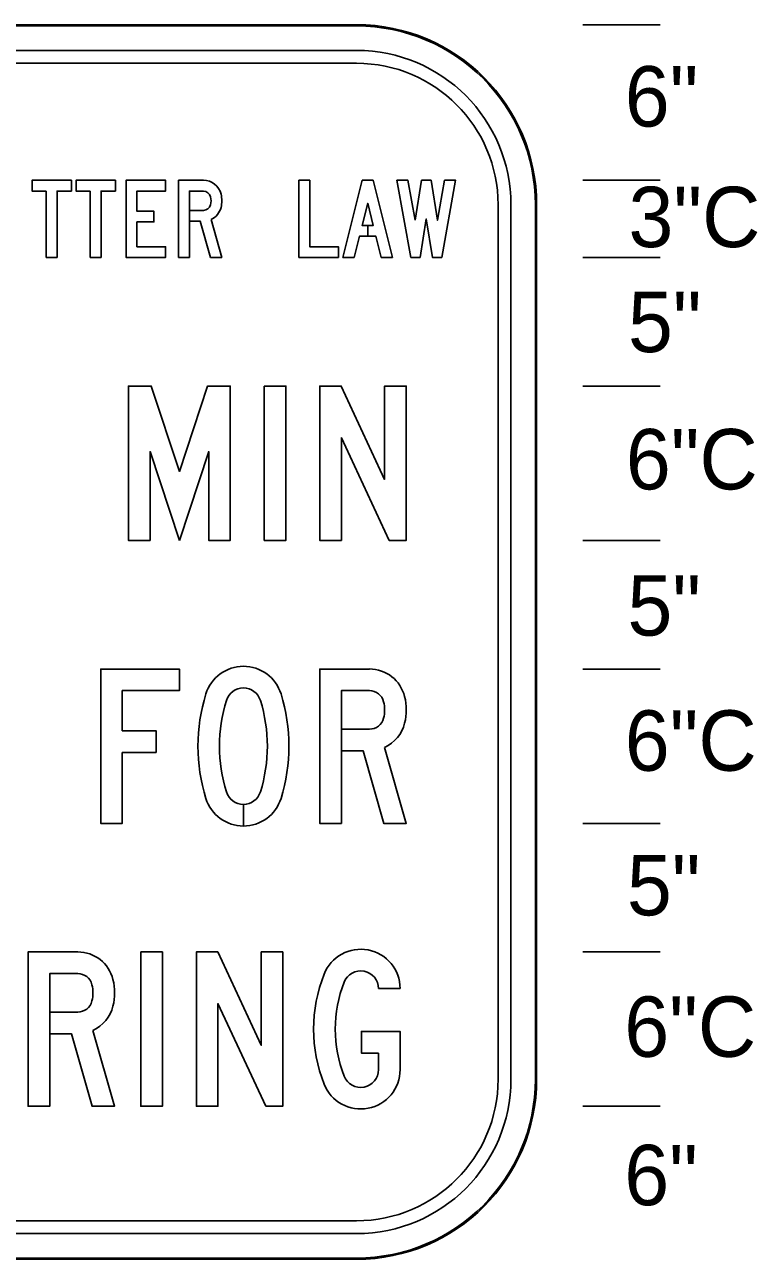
# Model space of a CAD drawing. Extents: x 0 to 770, y 0 to 495.
# Drawn here: x 668.7 to 711.2, y 64.1 to 135.7 of the extents above; entities that cross this region are included whole.
import ezdxf

# ---------------------------------------------------------------- set-up
doc = ezdxf.new("R2010")
doc.units = 0
for name, color, linetype in [('GSBWFill', 7, 'Continuous'), ('GSColorFill', 7, 'Continuous'), ('GSDims', 7, 'Continuous'), ('GSOutline', 7, 'Continuous'), ('TextStructures', 7, 'Continuous')]:
    doc.layers.add(name, color=color, linetype=linetype)

msp = doc.modelspace()

# ---------------------------------------------------------------- linework, layer by layer
at = {"layer": 'GSBWFill'}
for p, q in [((687.955, 135.665), (646.215, 135.665)), ((687.955, 134.174), (646.215, 134.174)), ((646.215, 133.429), (687.955, 133.429)), ((696.154, 125.23), (696.154, 74.545)), ((696.899, 74.545), (696.899, 125.23)), ((698.39, 74.545), (698.39, 125.23)), ((679.076, 124.902), (679.076, 124.902)), ((688.697, 94.834), (688.697, 94.834)), ((681.396, 90.474), (681.396, 89.222)), ((681.396, 89.222), (681.396, 90.474)), ((689.222, 79.8), (690.474, 79.8)), ((671.792, 78.436), (671.792, 78.436)), ((689.222, 76.066), (689.222, 75.104)), ((687.955, 66.346), (646.222, 66.346)), ((646.222, 65.601), (687.955, 65.601)), ((646.215, 64.11), (687.955, 64.11))]:
    msp.add_line(p, q, dxfattribs=at)
for points in [[(669.969, 126.02), (669.142, 126.02), (669.142, 126.646), (671.423, 126.646), (671.423, 126.02), (670.595, 126.02), (670.595, 122.174), (669.969, 122.174)], [(672.518, 126.02), (671.691, 126.02), (671.691, 126.646), (673.972, 126.646), (673.972, 126.02), (673.144, 126.02), (673.144, 122.174), (672.518, 122.174)], [(675.224, 122.8), (675.224, 124.231), (676.204, 124.231), (676.204, 124.857), (675.224, 124.857), (675.224, 126.02), (676.879, 126.02), (676.879, 126.646), (674.598, 126.646), (674.598, 122.174), (676.879, 122.174), (676.879, 122.8)], [(684.615, 126.646), (685.242, 126.646), (685.242, 122.8), (686.896, 122.8), (686.896, 122.174), (684.615, 122.174)], [(688.596, 124.03), (688.274, 124.03), (688.596, 125.317), (688.917, 124.03), (688.596, 124.03), (688.596, 123.404), (689.074, 123.404), (689.381, 122.174), (690.027, 122.174), (688.909, 126.646), (688.283, 126.646), (687.165, 122.174), (687.81, 122.174), (688.117, 123.404), (688.596, 123.404)], [(691.348, 124.332), (691.718, 126.646), (692.271, 126.646), (692.641, 124.332), (693.058, 126.646), (693.694, 126.646), (692.889, 122.174), (692.352, 122.174), (691.995, 124.41), (691.637, 122.174), (691.1, 122.174), (690.295, 126.646), (690.931, 126.646)], [(677.684, 105.776), (679.383, 110.926), (679.383, 105.776), (680.635, 105.776), (680.635, 114.72), (679.317, 114.72), (677.684, 109.772), (676.051, 114.72), (674.732, 114.72), (674.732, 105.776), (675.984, 105.776), (675.984, 110.926)], [(682.603, 114.72), (683.855, 114.72), (683.855, 105.776), (682.603, 105.776)], [(689.848, 105.776), (690.832, 105.776), (690.832, 114.72), (689.58, 114.72), (689.58, 109.315), (687.06, 114.72), (685.823, 114.72), (685.823, 105.776), (687.075, 105.776), (687.075, 111.724)], [(674.374, 93.493), (676.334, 93.493), (676.334, 94.745), (674.374, 94.745), (674.374, 97.07), (677.684, 97.07), (677.684, 98.322), (673.122, 98.322), (673.122, 89.378), (674.374, 89.378)], [(675.448, 81.925), (676.7, 81.925), (676.7, 72.98), (675.448, 72.98)], [(682.692, 72.98), (683.676, 72.98), (683.676, 81.925), (682.424, 81.925), (682.424, 76.52), (679.905, 81.925), (678.668, 81.925), (678.668, 72.98), (679.92, 72.98), (679.92, 78.928)]]:
    msp.add_lwpolyline(points, close=True, dxfattribs=at)
for points in [[(679.076, 126.02), (678.265, 126.02), (678.265, 122.174), (677.639, 122.174), (677.639, 126.646), (679.076, 126.646)], [(679.517, 124.373), (680.143, 122.174), (679.492, 122.174), (678.894, 124.276), (678.265, 124.276), (678.265, 124.902), (679.076, 124.902)], [(688.697, 97.07), (687.075, 97.07), (687.075, 89.378), (685.823, 89.378), (685.823, 98.322), (688.697, 98.322)], [(689.58, 93.776), (690.832, 89.378), (689.53, 89.378), (688.333, 93.582), (687.076, 93.582), (687.076, 94.834), (688.697, 94.834)], [(671.792, 80.672), (670.17, 80.672), (670.17, 72.98), (668.918, 72.98), (668.918, 81.925), (671.792, 81.925)], [(672.675, 77.378), (673.927, 72.98), (672.625, 72.98), (671.428, 77.184), (670.171, 77.184), (670.171, 78.436), (671.792, 78.436)], [(690.474, 75.104), (690.474, 77.318), (688.238, 77.318), (688.238, 76.066), (689.222, 76.066)]]:
    msp.add_lwpolyline(points, dxfattribs=at)
for centre, radius, start, end in [((687.955, 125.23), 10.435, 0, 90), ((687.955, 125.23), 8.944, 0, 90), ((687.955, 125.23), 8.199, 0, 90), ((679.076, 125.595), 1.051, 13.88654, 90), ((679.076, 125.595), 0.425, 13.88654, 90), ((679.076, 125.327), 0.425, 270, 346.11346), ((678.533, 125.461), 0.984, 346.11346, 13.88654), ((678.533, 125.461), 1.61, 346.11346, 13.88654), ((679.076, 125.327), 1.051, 294.82206, 346.11346), ((681.396, 96.198), 2.281, 17.32827, 162.67173), ((688.697, 96.221), 2.102, 13.88654, 90), ((688.921, 93.85), 10.164, 162.67173, 197.32827), ((681.396, 96.198), 1.029, 17.32827, 162.67173), ((673.87, 93.85), 10.164, 342.67173, 17.32827), ((688.697, 96.221), 0.85, 13.88654, 90), ((687.612, 95.952), 3.22, 346.11346, 13.88654), ((688.921, 93.85), 8.911, 162.67173, 197.32827), ((673.87, 93.85), 8.911, 342.67173, 17.32827), ((687.612, 95.952), 1.968, 346.11346, 13.88654), ((688.697, 95.684), 0.85, 270, 346.11346), ((688.697, 95.684), 2.102, 294.82206, 346.11346), ((681.396, 91.502), 1.029, 197.32827, 270), ((681.396, 91.502), 1.029, 270.02491, 342.67173), ((681.396, 91.502), 2.281, 197.32827, 270), ((681.396, 91.502), 2.281, 270.01123, 342.67173), ((671.792, 79.823), 2.102, 13.88654, 90), ((688.193, 79.8), 2.281, 0, 158.43141), ((671.792, 79.823), 0.85, 13.88654, 90), ((670.707, 79.554), 3.22, 346.11346, 13.88654), ((694.133, 77.452), 8.668, 158.43141, 201.5686), ((694.133, 77.452), 7.415, 158.4314, 201.56859), ((688.193, 79.8), 1.029, 0, 158.43141), ((670.707, 79.554), 1.968, 346.11346, 13.88654), ((671.792, 79.286), 0.85, 270, 346.11346), ((671.792, 79.286), 2.102, 294.82206, 346.11346), ((688.193, 75.104), 2.281, 201.56859, 0), ((688.193, 75.104), 1.029, 201.56859, 0), ((687.955, 74.545), 8.944, 270, 0), ((687.955, 74.545), 8.199, 270, 0), ((687.955, 74.545), 10.435, 270, 0)]:
    msp.add_arc(centre, radius, start, end, dxfattribs=at)
at = {"layer": 'GSColorFill'}
for p, q in [((687.955, 135.665), (646.215, 135.665)), ((687.955, 135.665), (646.215, 135.665)), ((646.215, 135.59), (687.955, 135.59)), ((687.955, 134.174), (646.215, 134.174)), ((646.215, 133.429), (687.955, 133.429)), ((696.154, 125.23), (696.154, 74.545)), ((696.899, 74.545), (696.899, 125.23)), ((698.315, 125.23), (698.315, 74.545)), ((698.39, 74.545), (698.39, 125.23)), ((698.39, 74.545), (698.39, 125.23)), ((679.076, 124.902), (679.076, 124.902)), ((688.697, 94.834), (688.697, 94.834)), ((681.396, 90.474), (681.396, 89.222)), ((681.396, 89.222), (681.396, 90.474)), ((689.222, 79.8), (690.474, 79.8)), ((671.792, 78.436), (671.792, 78.436)), ((689.222, 76.066), (689.222, 75.104)), ((687.955, 66.346), (646.222, 66.346)), ((646.222, 65.601), (687.955, 65.601)), ((687.955, 64.185), (646.215, 64.185)), ((646.215, 64.11), (687.955, 64.11)), ((646.215, 64.11), (687.955, 64.11))]:
    msp.add_line(p, q, dxfattribs=at)
for points in [[(669.969, 126.02), (669.142, 126.02), (669.142, 126.646), (671.423, 126.646), (671.423, 126.02), (670.595, 126.02), (670.595, 122.174), (669.969, 122.174)], [(672.518, 126.02), (671.691, 126.02), (671.691, 126.646), (673.972, 126.646), (673.972, 126.02), (673.144, 126.02), (673.144, 122.174), (672.518, 122.174)], [(675.224, 122.8), (675.224, 124.231), (676.204, 124.231), (676.204, 124.857), (675.224, 124.857), (675.224, 126.02), (676.879, 126.02), (676.879, 126.646), (674.598, 126.646), (674.598, 122.174), (676.879, 122.174), (676.879, 122.8)], [(684.615, 126.646), (685.242, 126.646), (685.242, 122.8), (686.896, 122.8), (686.896, 122.174), (684.615, 122.174)], [(688.596, 124.03), (688.274, 124.03), (688.596, 125.317), (688.917, 124.03), (688.596, 124.03), (688.596, 123.404), (689.074, 123.404), (689.381, 122.174), (690.027, 122.174), (688.909, 126.646), (688.283, 126.646), (687.165, 122.174), (687.81, 122.174), (688.117, 123.404), (688.596, 123.404)], [(691.348, 124.332), (691.718, 126.646), (692.271, 126.646), (692.641, 124.332), (693.058, 126.646), (693.694, 126.646), (692.889, 122.174), (692.352, 122.174), (691.995, 124.41), (691.637, 122.174), (691.1, 122.174), (690.295, 126.646), (690.931, 126.646)], [(677.684, 105.776), (679.383, 110.926), (679.383, 105.776), (680.635, 105.776), (680.635, 114.72), (679.317, 114.72), (677.684, 109.772), (676.051, 114.72), (674.732, 114.72), (674.732, 105.776), (675.984, 105.776), (675.984, 110.926)], [(682.603, 114.72), (683.855, 114.72), (683.855, 105.776), (682.603, 105.776)], [(689.848, 105.776), (690.832, 105.776), (690.832, 114.72), (689.58, 114.72), (689.58, 109.315), (687.06, 114.72), (685.823, 114.72), (685.823, 105.776), (687.075, 105.776), (687.075, 111.724)], [(674.374, 93.493), (676.334, 93.493), (676.334, 94.745), (674.374, 94.745), (674.374, 97.07), (677.684, 97.07), (677.684, 98.322), (673.122, 98.322), (673.122, 89.378), (674.374, 89.378)], [(675.448, 81.925), (676.7, 81.925), (676.7, 72.98), (675.448, 72.98)], [(682.692, 72.98), (683.676, 72.98), (683.676, 81.925), (682.424, 81.925), (682.424, 76.52), (679.905, 81.925), (678.668, 81.925), (678.668, 72.98), (679.92, 72.98), (679.92, 78.928)]]:
    msp.add_lwpolyline(points, close=True, dxfattribs=at)
for points in [[(679.076, 126.02), (678.265, 126.02), (678.265, 122.174), (677.639, 122.174), (677.639, 126.646), (679.076, 126.646)], [(679.517, 124.373), (680.143, 122.174), (679.492, 122.174), (678.894, 124.276), (678.265, 124.276), (678.265, 124.902), (679.076, 124.902)], [(688.697, 97.07), (687.075, 97.07), (687.075, 89.378), (685.823, 89.378), (685.823, 98.322), (688.697, 98.322)], [(689.58, 93.776), (690.832, 89.378), (689.53, 89.378), (688.333, 93.582), (687.076, 93.582), (687.076, 94.834), (688.697, 94.834)], [(671.792, 80.672), (670.17, 80.672), (670.17, 72.98), (668.918, 72.98), (668.918, 81.925), (671.792, 81.925)], [(672.675, 77.378), (673.927, 72.98), (672.625, 72.98), (671.428, 77.184), (670.171, 77.184), (670.171, 78.436), (671.792, 78.436)], [(690.474, 75.104), (690.474, 77.318), (688.238, 77.318), (688.238, 76.066), (689.222, 76.066)]]:
    msp.add_lwpolyline(points, dxfattribs=at)
for centre, radius, start, end in [((687.955, 125.23), 10.435, 0, 90), ((687.955, 125.23), 10.435, 0, 90), ((687.955, 125.23), 10.361, 0, 90), ((687.955, 125.23), 8.944, 0, 90), ((687.955, 125.23), 8.199, 0, 90), ((679.076, 125.595), 1.051, 13.88654, 90), ((679.076, 125.595), 0.425, 13.88654, 90), ((679.076, 125.327), 0.425, 270, 346.11346), ((678.533, 125.461), 0.984, 346.11346, 13.88654), ((678.533, 125.461), 1.61, 346.11346, 13.88654), ((679.076, 125.327), 1.051, 294.82206, 346.11346), ((681.396, 96.198), 2.281, 17.32827, 162.67173), ((688.697, 96.221), 2.102, 13.88654, 90), ((688.921, 93.85), 10.164, 162.67173, 197.32827), ((681.396, 96.198), 1.029, 17.32827, 162.67173), ((673.87, 93.85), 10.164, 342.67173, 17.32827), ((688.697, 96.221), 0.85, 13.88654, 90), ((687.612, 95.952), 3.22, 346.11346, 13.88654), ((688.921, 93.85), 8.911, 162.67173, 197.32827), ((673.87, 93.85), 8.911, 342.67173, 17.32827), ((687.612, 95.952), 1.968, 346.11346, 13.88654), ((688.697, 95.684), 0.85, 270, 346.11346), ((688.697, 95.684), 2.102, 294.82206, 346.11346), ((681.396, 91.502), 1.029, 197.32827, 270), ((681.396, 91.502), 1.029, 270.02491, 342.67173), ((681.396, 91.502), 2.281, 197.32827, 270), ((681.396, 91.502), 2.281, 270.01123, 342.67173), ((671.792, 79.823), 2.102, 13.88654, 90), ((688.193, 79.8), 2.281, 0, 158.43141), ((671.792, 79.823), 0.85, 13.88654, 90), ((670.707, 79.554), 3.22, 346.11346, 13.88654), ((694.133, 77.452), 8.668, 158.43141, 201.5686), ((694.133, 77.452), 7.415, 158.4314, 201.56859), ((688.193, 79.8), 1.029, 0, 158.43141), ((670.707, 79.554), 1.968, 346.11346, 13.88654), ((671.792, 79.286), 0.85, 270, 346.11346), ((671.792, 79.286), 2.102, 294.82206, 346.11346), ((688.193, 75.104), 2.281, 201.56859, 0), ((688.193, 75.104), 1.029, 201.56859, 0), ((687.955, 74.545), 10.435, 270, 0), ((687.955, 74.545), 8.944, 270, 0), ((687.955, 74.545), 8.199, 270, 0), ((687.955, 74.545), 10.435, 270, 0), ((687.955, 74.545), 10.361, 270, 0)]:
    msp.add_arc(centre, radius, start, end, dxfattribs=at)
at = {"layer": 'GSDims'}
for p, q in [((701.073, 135.665), (705.545, 135.665)), ((701.073, 126.646), (705.545, 126.646)), ((701.073, 126.646), (705.545, 126.646)), ((701.073, 122.174), (705.545, 122.174)), ((701.073, 122.174), (705.545, 122.174)), ((701.073, 114.72), (705.545, 114.72)), ((701.073, 114.72), (705.545, 114.72)), ((701.073, 105.776), (705.545, 105.776)), ((701.073, 105.776), (705.545, 105.776)), ((701.073, 98.322), (705.545, 98.322)), ((701.073, 98.322), (705.545, 98.322)), ((701.073, 89.378), (705.545, 89.378)), ((701.073, 89.378), (705.545, 89.378)), ((701.073, 81.925), (705.545, 81.925)), ((701.073, 81.925), (705.545, 81.925)), ((701.073, 72.98), (705.545, 72.98)), ((701.073, 72.98), (705.545, 72.98))]:
    msp.add_line(p, q, dxfattribs=at)
at = {"layer": 'GSOutline'}
for p, q in [((687.955, 135.665), (646.215, 135.665)), ((687.955, 134.174), (646.215, 134.174)), ((687.955, 133.429), (646.215, 133.429)), ((679.076, 126.646), (677.639, 126.646)), ((679.076, 126.02), (679.076, 126.02)), ((696.154, 74.545), (696.154, 125.23)), ((696.899, 74.545), (696.899, 125.23)), ((698.39, 74.545), (698.39, 125.23)), ((688.697, 98.322), (685.823, 98.322)), ((688.697, 97.07), (688.697, 97.07)), ((671.792, 81.925), (668.918, 81.925)), ((671.792, 80.672), (671.792, 80.672)), ((689.222, 79.8), (690.474, 79.8)), ((689.222, 76.066), (689.222, 75.104)), ((646.215, 66.346), (687.955, 66.346)), ((646.215, 65.601), (687.955, 65.601)), ((646.215, 64.11), (687.955, 64.11))]:
    msp.add_line(p, q, dxfattribs=at)
for points in [[(669.969, 126.02), (669.142, 126.02), (669.142, 126.646), (671.423, 126.646), (671.423, 126.02), (670.595, 126.02), (670.595, 122.174), (669.969, 122.174)], [(672.518, 126.02), (671.691, 126.02), (671.691, 126.646), (673.972, 126.646), (673.972, 126.02), (673.144, 126.02), (673.144, 122.174), (672.518, 122.174)], [(675.224, 122.8), (675.224, 124.231), (676.204, 124.231), (676.204, 124.857), (675.224, 124.857), (675.224, 126.02), (676.879, 126.02), (676.879, 126.646), (674.598, 126.646), (674.598, 122.174), (676.879, 122.174), (676.879, 122.8)], [(684.615, 126.646), (685.242, 126.646), (685.242, 122.8), (686.896, 122.8), (686.896, 122.174), (684.615, 122.174)], [(688.117, 123.404), (689.074, 123.404), (689.381, 122.174), (690.027, 122.174), (688.909, 126.646), (688.283, 126.646), (687.165, 122.174), (687.81, 122.174)], [(691.348, 124.332), (691.718, 126.646), (692.271, 126.646), (692.641, 124.332), (693.058, 126.646), (693.694, 126.646), (692.889, 122.174), (692.352, 122.174), (691.995, 124.41), (691.637, 122.174), (691.1, 122.174), (690.295, 126.646), (690.931, 126.646)], [(688.917, 124.03), (688.596, 125.317), (688.274, 124.03)], [(677.684, 105.776), (679.383, 110.926), (679.383, 105.776), (680.635, 105.776), (680.635, 114.72), (679.317, 114.72), (677.684, 109.772), (676.051, 114.72), (674.732, 114.72), (674.732, 105.776), (675.984, 105.776), (675.984, 110.926)], [(682.603, 114.72), (683.855, 114.72), (683.855, 105.776), (682.603, 105.776)], [(689.848, 105.776), (690.832, 105.776), (690.832, 114.72), (689.58, 114.72), (689.58, 109.315), (687.06, 114.72), (685.823, 114.72), (685.823, 105.776), (687.075, 105.776), (687.075, 111.724)], [(674.374, 93.493), (676.334, 93.493), (676.334, 94.745), (674.374, 94.745), (674.374, 97.07), (677.684, 97.07), (677.684, 98.322), (673.122, 98.322), (673.122, 89.378), (674.374, 89.378)], [(675.448, 81.925), (676.7, 81.925), (676.7, 72.98), (675.448, 72.98)], [(682.692, 72.98), (683.676, 72.98), (683.676, 81.925), (682.424, 81.925), (682.424, 76.52), (679.905, 81.925), (678.668, 81.925), (678.668, 72.98), (679.92, 72.98), (679.92, 78.928)]]:
    msp.add_lwpolyline(points, close=True, dxfattribs=at)
for points in [[(677.639, 126.646), (677.639, 122.174), (678.265, 122.174), (678.265, 124.276), (678.894, 124.276), (679.492, 122.174), (680.143, 122.174), (679.517, 124.373)], [(679.076, 126.02), (678.265, 126.02), (678.265, 124.902), (679.076, 124.902)], [(685.823, 98.322), (685.823, 89.378), (687.075, 89.378), (687.075, 93.582), (688.333, 93.582), (689.53, 89.378), (690.832, 89.378), (689.58, 93.776)], [(688.697, 97.07), (687.075, 97.07), (687.075, 94.834), (688.697, 94.834)], [(668.918, 81.925), (668.918, 72.98), (670.17, 72.98), (670.17, 77.184), (671.428, 77.184), (672.625, 72.98), (673.927, 72.98), (672.675, 77.378)], [(671.792, 80.672), (670.17, 80.672), (670.17, 78.436), (671.792, 78.436)], [(690.474, 75.104), (690.474, 77.318), (688.238, 77.318), (688.238, 76.066), (689.222, 76.066)]]:
    msp.add_lwpolyline(points, dxfattribs=at)
for centre, radius, start, end in [((687.955, 125.23), 10.435, 0, 90), ((687.955, 125.23), 8.944, 0, 90), ((687.955, 125.23), 8.199, 0, 90), ((679.076, 125.595), 1.051, 13.88654, 90), ((679.076, 125.595), 0.425, 13.88654, 90), ((679.076, 125.327), 0.425, 270, 346.11346), ((678.533, 125.461), 0.984, 346.11346, 13.88654), ((678.533, 125.461), 1.61, 346.11346, 13.88654), ((679.076, 125.327), 1.051, 294.82207, 346.11346), ((681.396, 96.198), 2.281, 17.32827, 162.67173), ((688.697, 96.221), 2.102, 13.88654, 90), ((688.921, 93.85), 10.164, 162.67173, 197.32827), ((681.396, 96.198), 1.029, 17.32827, 162.67173), ((673.87, 93.85), 10.164, 342.67173, 17.32827), ((688.697, 96.221), 0.85, 13.88654, 90), ((687.612, 95.952), 3.22, 346.11346, 13.88654), ((688.921, 93.85), 8.911, 162.67173, 197.32827), ((673.87, 93.85), 8.911, 342.67173, 17.32827), ((687.612, 95.952), 1.968, 346.11346, 13.88654), ((688.697, 95.684), 0.85, 270, 346.11346), ((688.697, 95.684), 2.102, 294.82207, 346.11346), ((681.396, 91.502), 1.029, 197.32827, 342.67173), ((681.396, 91.502), 2.281, 197.32827, 342.67173), ((671.792, 79.823), 2.102, 13.88654, 90), ((688.193, 79.8), 2.281, 0, 158.43141), ((671.792, 79.823), 0.85, 13.88654, 90), ((670.707, 79.554), 3.22, 346.11346, 13.88654), ((694.133, 77.452), 8.668, 158.43141, 201.5686), ((694.133, 77.452), 7.415, 158.4314, 201.56859), ((688.193, 79.8), 1.029, 0, 158.43141), ((670.707, 79.554), 1.968, 346.11346, 13.88654), ((671.792, 79.286), 0.85, 270, 346.11346), ((671.792, 79.286), 2.102, 294.82207, 346.11346), ((688.193, 75.104), 2.281, 201.56859, 0), ((688.193, 75.104), 1.029, 201.56859, 0), ((687.955, 74.545), 8.944, 270, 0), ((687.955, 74.545), 8.199, 270, 0), ((687.955, 74.545), 10.435, 270, 0)]:
    msp.add_arc(centre, radius, start, end, dxfattribs=at)

# ---------------------------------------------------------------- texts
at = {"layer": 'TextStructures'}
for s, p in [('6"', (703.499, 129.763)), ('3"C', (703.713, 122.773)), ('5"', (703.682, 116.688)), ('6"C', (703.56, 108.733)), ('5"', (703.652, 100.259)), ('6"C', (703.499, 92.427)), ('5"', (703.621, 84.045)), ('6"C', (703.469, 75.846)), ('6"', (703.469, 67.244))]:
    msp.add_text(s, height=3.5, dxfattribs=at).set_placement(p)

doc.saveas('drawing.dxf')
